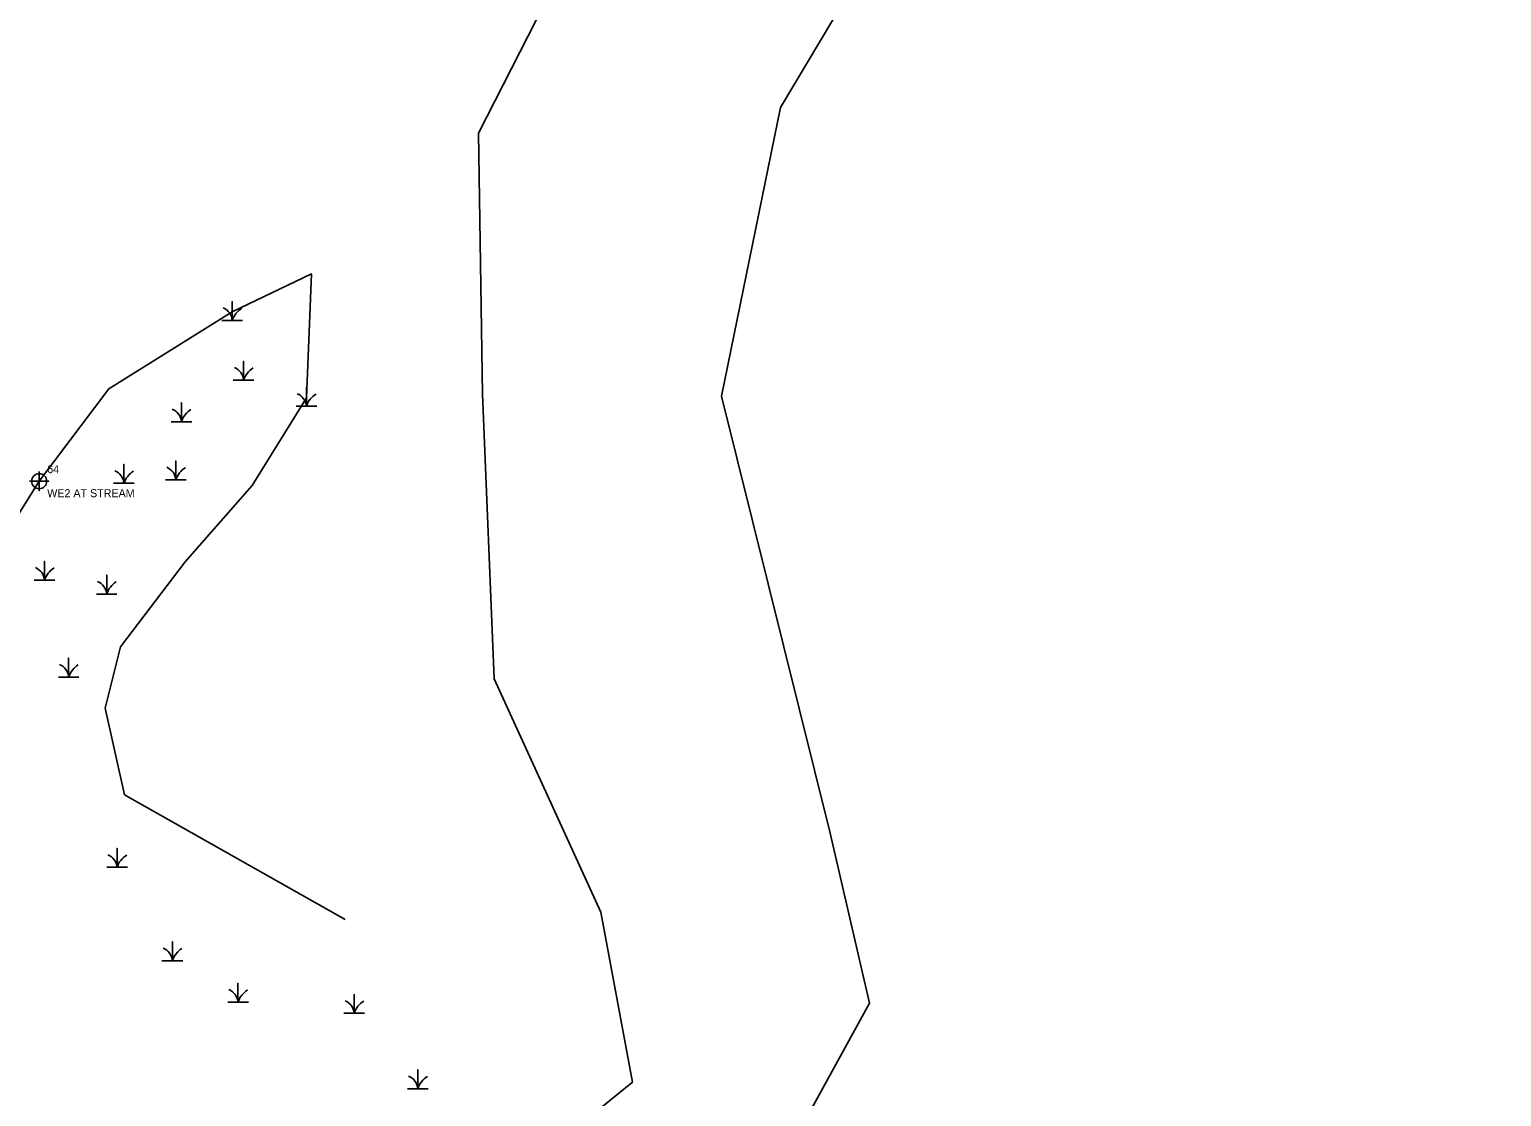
# Model space of a CAD drawing. Extents: x 2189822 to 2191198, y 387253 to 388663.
# Drawn here: x 2190456.6 to 2190916.4, y 387803.7 to 388136.9 of the extents above; entities that cross this region are included whole.
import ezdxf

# ---------------------------------------------------------------- set-up
doc = ezdxf.new("R2010")
doc.units = 0
for name, color, linetype in [('Structure020030_Alleghany', 7, 'Continuous'), ('Structure040008_Ashe', 7, 'Continuous'), ('Structure090007_Brunswick', 7, 'Continuous'), ('Structure300012_Duplin', 7, 'Continuous'), ('Structure620024_Moore', 7, 'Continuous'), ('Structure780124_Rockingham', 7, 'Continuous')]:
    doc.layers.add(name, color=color, linetype=linetype)

msp = doc.modelspace()

# ---------------------------------------------------------------- linework, layer by layer
at = {"layer": 'Structure020030_Alleghany'}
msp.add_lwpolyline([(2190459.66, 387998.83), (2190459.66, 387992.83), (2190459.66, 387995.83), (2190462.66, 387995.83), (2190456.66, 387995.83)], dxfattribs=at)
msp.add_circle((2190459.66, 387995.83), 2.34, dxfattribs=at)
at = {"layer": 'Structure300012_Duplin'}
for points in [[(2190719.63, 387525.44), (2190637.58, 387595.81), (2190615.99, 387660.63), (2190664.72, 387734.09), (2190719.01, 387832.86), (2190706.67, 387885.95), (2190672.74, 388022.38), (2190691.25, 388112.51), (2190740.6, 388195.23), (2190831.91, 388239.06), (2190949.74, 388250.79), (2191071.27, 388298.94), (2191159.49, 388358.82), (2191198.36, 388416.84)], [(2190909.02, 388316.22), (2190800.44, 388283.5), (2190731.35, 388245.85), (2190706.67, 388239.06), (2190667.81, 388207.57), (2190625.24, 388160.04), (2190596.86, 388104.48), (2190598.1, 388023), (2190601.8, 387934.1), (2190635.11, 387861.26), (2190644.98, 387808.17), (2190567.25, 387745.2), (2190533.32, 387681), (2190546.89, 387613.72), (2190580.2, 387545.81), (2190636.96, 387481.61), (2190661.02, 387459.39)]]:
    msp.add_lwpolyline(points, dxfattribs=at)
at = {"layer": 'Structure620024_Moore'}
msp.add_line((2190486.31, 387897.92), (2190555.2, 387858.91), dxfattribs=at)
for points in [[(2190459.66, 387995.83), (2190481.36, 388024.7), (2190519.95, 388048.69), (2190544.73, 388060.58), (2190543.11, 388021.88), (2190526.19, 387994.47), (2190505.24, 387970.68), (2190485.1, 387944.08), (2190480.26, 387924.93), (2190486.31, 387897.92)], [(2190419.3, 387931.34), (2190459.66, 387995.83)]]:
    msp.add_lwpolyline(points, dxfattribs=at)
at = {"layer": 'Structure780124_Rockingham'}
for p, q in [((2190519.95, 388048.69), (2190519.95, 388048.69)), ((2190523.5, 388030.04), (2190523.5, 388030.04)), ((2190543.11, 388021.88), (2190543.11, 388021.88)), ((2190504.06, 388017.08), (2190504.06, 388017.08)), ((2190486.12, 387997.84), (2190486.12, 387997.84)), ((2190502.32, 387998.92), (2190502.32, 387998.92)), ((2190502.32, 387998.92), (2190502.32, 387998.92)), ((2190461.29, 387967.59), (2190461.29, 387967.59)), ((2190480.73, 387963.27), (2190480.73, 387963.27)), ((2190468.85, 387937.34), (2190468.85, 387937.34)), ((2190468.85, 387937.34), (2190468.85, 387937.34)), ((2190483.97, 387877.93), (2190483.97, 387877.93)), ((2190501.24, 387848.76), (2190501.24, 387848.76)), ((2190521.75, 387835.8), (2190521.75, 387835.8)), ((2190558.04, 387832.35), (2190558.04, 387832.35)), ((2190577.89, 387808.79), (2190577.89, 387808.79))]:
    msp.add_line(p, q, dxfattribs=at)
for points in [[(2190516.72, 388046.02), (2190519.95, 388046.02), (2190519.95, 388051.94), (2190519.95, 388046.02), (2190523.17, 388046.02)], [(2190520.27, 388027.37), (2190523.5, 388027.37), (2190523.5, 388033.29), (2190523.5, 388027.37), (2190526.72, 388027.37)], [(2190539.89, 388019.21), (2190543.11, 388019.21), (2190543.11, 388025.13), (2190543.11, 388019.21), (2190546.34, 388019.21)], [(2190500.84, 388014.41), (2190504.06, 388014.41), (2190504.06, 388020.32), (2190504.06, 388014.41), (2190507.29, 388014.41)], [(2190482.9, 387995.17), (2190486.13, 387995.17), (2190486.13, 388001.08), (2190486.13, 387995.17), (2190489.35, 387995.17)], [(2190499.09, 387996.25), (2190502.32, 387996.25), (2190502.32, 388002.16), (2190502.32, 387996.25), (2190505.54, 387996.25)], [(2190499.09, 387996.25), (2190502.32, 387996.25), (2190502.32, 388002.16), (2190502.32, 387996.25), (2190505.54, 387996.25)], [(2190458.07, 387964.92), (2190461.29, 387964.92), (2190461.29, 387970.84), (2190461.29, 387964.92), (2190464.52, 387964.92)], [(2190477.5, 387960.6), (2190480.73, 387960.6), (2190480.73, 387966.51), (2190480.73, 387960.6), (2190483.95, 387960.6)], [(2190465.63, 387934.67), (2190468.85, 387934.67), (2190468.85, 387940.59), (2190468.85, 387934.67), (2190472.08, 387934.67)], [(2190465.63, 387934.67), (2190468.85, 387934.67), (2190468.85, 387940.59), (2190468.85, 387934.67), (2190472.08, 387934.67)], [(2190480.74, 387875.25), (2190483.97, 387875.25), (2190483.97, 387881.17), (2190483.97, 387875.25), (2190487.19, 387875.25)], [(2190498.01, 387846.09), (2190501.24, 387846.09), (2190501.24, 387852), (2190501.24, 387846.09), (2190504.47, 387846.09)], [(2190518.53, 387833.12), (2190521.75, 387833.12), (2190521.75, 387839.04), (2190521.75, 387833.12), (2190524.98, 387833.12)], [(2190554.82, 387829.68), (2190558.04, 387829.68), (2190558.04, 387835.59), (2190558.04, 387829.68), (2190561.27, 387829.68)], [(2190574.67, 387806.11), (2190577.89, 387806.11), (2190577.89, 387812.03), (2190577.89, 387806.11), (2190581.12, 387806.11)]]:
    msp.add_lwpolyline(points, dxfattribs=at)
for centre, radius, start, end in [((2190515.35, 388045.68), 4.61, 4.1403, 67.535), ((2190526.79, 388043.74), 7.21, 122.1274, 161.6222), ((2190518.9, 388027.04), 4.61, 4.1403, 67.535), ((2190530.34, 388025.1), 7.21, 122.1274, 161.6222), ((2190538.51, 388018.88), 4.61, 4.1403, 67.535), ((2190549.96, 388016.94), 7.21, 122.1274, 161.6222), ((2190499.46, 388014.07), 4.61, 4.1403, 67.535), ((2190510.9, 388012.13), 7.21, 122.1274, 161.6222), ((2190497.72, 387995.91), 4.61, 4.1403, 67.535), ((2190497.72, 387995.91), 4.61, 4.1403, 67.535), ((2190509.16, 387993.97), 7.21, 122.1274, 161.6222), ((2190509.16, 387993.97), 7.21, 122.1274, 161.6222), ((2190481.53, 387994.83), 4.61, 4.1403, 67.535), ((2190492.97, 387992.89), 7.21, 122.1274, 161.6222), ((2190456.69, 387964.59), 4.61, 4.1403, 67.535), ((2190468.13, 387962.65), 7.21, 122.1274, 161.6222), ((2190476.13, 387960.26), 4.61, 4.1403, 67.535), ((2190487.57, 387958.32), 7.21, 122.1274, 161.6222), ((2190464.25, 387934.34), 4.61, 4.1403, 67.535), ((2190464.25, 387934.34), 4.61, 4.1403, 67.535), ((2190475.69, 387932.4), 7.21, 122.1274, 161.6222), ((2190475.69, 387932.4), 7.21, 122.1274, 161.6222), ((2190479.37, 387874.92), 4.61, 4.1403, 67.535), ((2190490.81, 387872.98), 7.21, 122.1274, 161.6222), ((2190496.64, 387845.75), 4.61, 4.1403, 67.535), ((2190508.08, 387843.81), 7.21, 122.1274, 161.6222), ((2190517.15, 387832.79), 4.61, 4.1403, 67.535), ((2190528.59, 387830.85), 7.21, 122.1274, 161.6222), ((2190553.44, 387829.34), 4.61, 4.1403, 67.535), ((2190564.89, 387827.4), 7.21, 122.1274, 161.6222), ((2190573.29, 387805.78), 4.61, 4.1403, 67.535), ((2190584.73, 387803.84), 7.21, 122.1274, 161.6222)]:
    msp.add_arc(centre, radius, start, end, dxfattribs=at)

# ---------------------------------------------------------------- texts
at = {"layer": 'Structure040008_Ashe'}
msp.add_text('64', height=2.5, dxfattribs=at).set_placement((2190462.16, 387998.33))
at = {"layer": 'Structure090007_Brunswick'}
msp.add_text('WE2 AT STREAM', height=2.5, dxfattribs=at).set_placement((2190462.16, 387990.83))

doc.saveas('drawing.dxf')
